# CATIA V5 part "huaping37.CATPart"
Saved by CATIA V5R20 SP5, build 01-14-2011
Part number: 花瓶
Material "Water": density 1000 kg/m3
Material "Alcantara": density 900 kg/m3
Material "Fire Red": density 7860 kg/m3, Young's modulus 2e+11 Pa, Poisson ratio 0.266
Bounding box of the stored display mesh (mm): x -40 to 40, y -40 to 39.959, z 0 to 114.096
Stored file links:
  D:\180122237\yingliaoping\huaping37.CATPart
  C:\Program Files\Dassault Systemes\B20\intel_a\startup\materials\Catalog.CATMaterial
  C:\Program Files\Dassault Systemes\B20\intel_a\startup\materials\alcantara.jpg
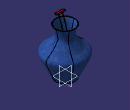
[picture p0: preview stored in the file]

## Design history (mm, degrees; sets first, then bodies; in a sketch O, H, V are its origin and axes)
Body1 (main body), material "Alcantara"
  Plane1: type Offset, RefPlane xy-plane, Offset 20
  Plane2: type Offset, RefPlane Plane1, Offset 25
  Plane3: type Offset, RefPlane Plane2, Offset 15
  Plane4: type Offset, RefPlane Plane3, Offset 15
  Plane5: type Offset, RefPlane Plane4, Offset 20
  Sketch1 on Plane5, origin (0, 0, 95), H (1, 0, 0), V (0, 1, 0)
    circle A1 centre (0, 0) radius 20
  Sketch2 on Plane4, origin (0, 0, 75), H (1, 0, 0), V (0, 1, 0)
    circle A1 centre (0, 0) radius 15
    radius A1 = 15
  Sketch3 on Plane3, origin (0, 0, 60), H (1, 0, 0), V (0, 1, 0)
    circle A1 centre (0, 0) radius 25
    radius A1 = 25
  Sketch4 on Plane2, origin (0, 0, 45), H (1, 0, 0), V (0, 1, 0)
    circle A1 centre (0, 0) radius 40
  Sketch5 on Plane1, origin (0, 0, 20), H (1, 0, 0), V (0, 1, 0)
    circle A1 centre (0, 0) radius 30
  Sketch6 on xy-plane, origin (0, 0, 0), H (1, 0, 0), V (0, 1, 0)
    circle A1 centre (0, 0) radius 20
  Loft1: solid, Sections (Sketch1; Sketch2; Sketch3; Sketch4; Sketch5; Sketch6)
  Shell1: ExtOffset 0, Face face of Loft1, IntOffset 1
Body2, material "Water"
  Sketch7 on yz-plane, origin (0, 0, 0), H (0, 1, 0), V (0, 0, 1)
    axis line L1 (0, 108.5052) -> (0, -10.8485)
    point P1 (0, 108.5052)
    line L2 (0, 29.7425) -> (26.6663, 29.7425)
    point P3 (0, 29.7425)
    point P4 (26.6663, 29.7425)
    spline S1 through (26.6663, 29.7425) (23.4338, 10.6567) (18.3155, 0)
    line L3 (18.3155, 0) -> (0, 0)
    point P5 (18.3155, 0)
    point P6 (26.6663, 29.7425)
    point P7 (18.3155, 0)
    coincidence: P1 V, P3 L1, P6 P4, P7 H, P7 P5
    vertical: L1 V
    horizontal: L2 H, L3 H
  Shaft1: profile Sketch7, axis Sketch7.L1, angle 360
Body3, material "Fire Red"
  Sketch8 on yz-plane, origin (0, 0, 0), H (0, 1, 0), V (0, 0, 1)
    spline S1 through (-10, 110) (0, 80) (-10, 10)
  Plane6: type Normal, Curve Sketch8, RefPoint vertex of Sketch8
  Sketch9 on Plane6, origin (0, -45.3382, 92.7204), H (1, 0, 0), V (0, 0.8984, 0.4393)
    circle A1 centre (0, 39.0159) radius 0.5
    point P1 (0, 39.0159)
    radius A1 = 0.5
    coincidence: P1 V
  Rib1: profile Sketch9, centre curve Sketch8, thin wall 1
  Sketch10 on Plane6, origin (0, -45.3382, 92.7204), H (1, 0, 0), V (0, 0.8984, 0.4393)
    point P1 (0, 39.3875)
    point P2 (5.177, 37.9856)
    point P3 (3.8026, 43.17)
    point P4 (-1.3744, 44.5719)
    point P5 (-5.177, 40.7895)
    point P6 (-3.8026, 35.6051)
    point P7 (1.3744, 34.2032)
    point P8 (4.4898, 40.5778)
    line L1 (5.177, 37.9856) -> (3.8026, 43.17)
    line L2 (3.8026, 43.17) -> (-1.3744, 44.5719)
    line L3 (-1.3744, 44.5719) -> (-5.177, 40.7895)
    line L4 (-5.177, 40.7895) -> (-3.8026, 35.6051)
    line L5 (-3.8026, 35.6051) -> (1.3744, 34.2032)
    line L6 (1.3744, 34.2032) -> (5.177, 37.9856)
    construction line L7 (0, 39.3875) -> (4.4898, 40.5778)
    construction circle A1 centre (0, 39.3875) radius 5.3635
    construction arc A2 centre (-3.8026, 35.6051) radius 5.3635 from (-5.177, 40.7895) to (1.3744, 34.2032) cw
    construction arc A3 centre (3.8026, 43.17) radius 5.3635 from (-1.3744, 44.5719) to (5.177, 37.9856) ccw
    coincidence: P1 V, A1 P2, A1 P3, A1 P4, A1 P5, A1 P6, A1 P7, A2 P1, A3 P1
    midpoint: P8 L1
    parallelism: L1 L4
  Pad1: profile Sketch10, direction (0, -0.4393, 0.8984), length 2
  Translate1: Direction face of Shaft1 from Sketch7.L2, ToTransfor Pad1, Length 0
  Translate2: Direction yz-plane, ToTransfor Translate1, Length 4
  Mirror1: of the body so far, about yz-plane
